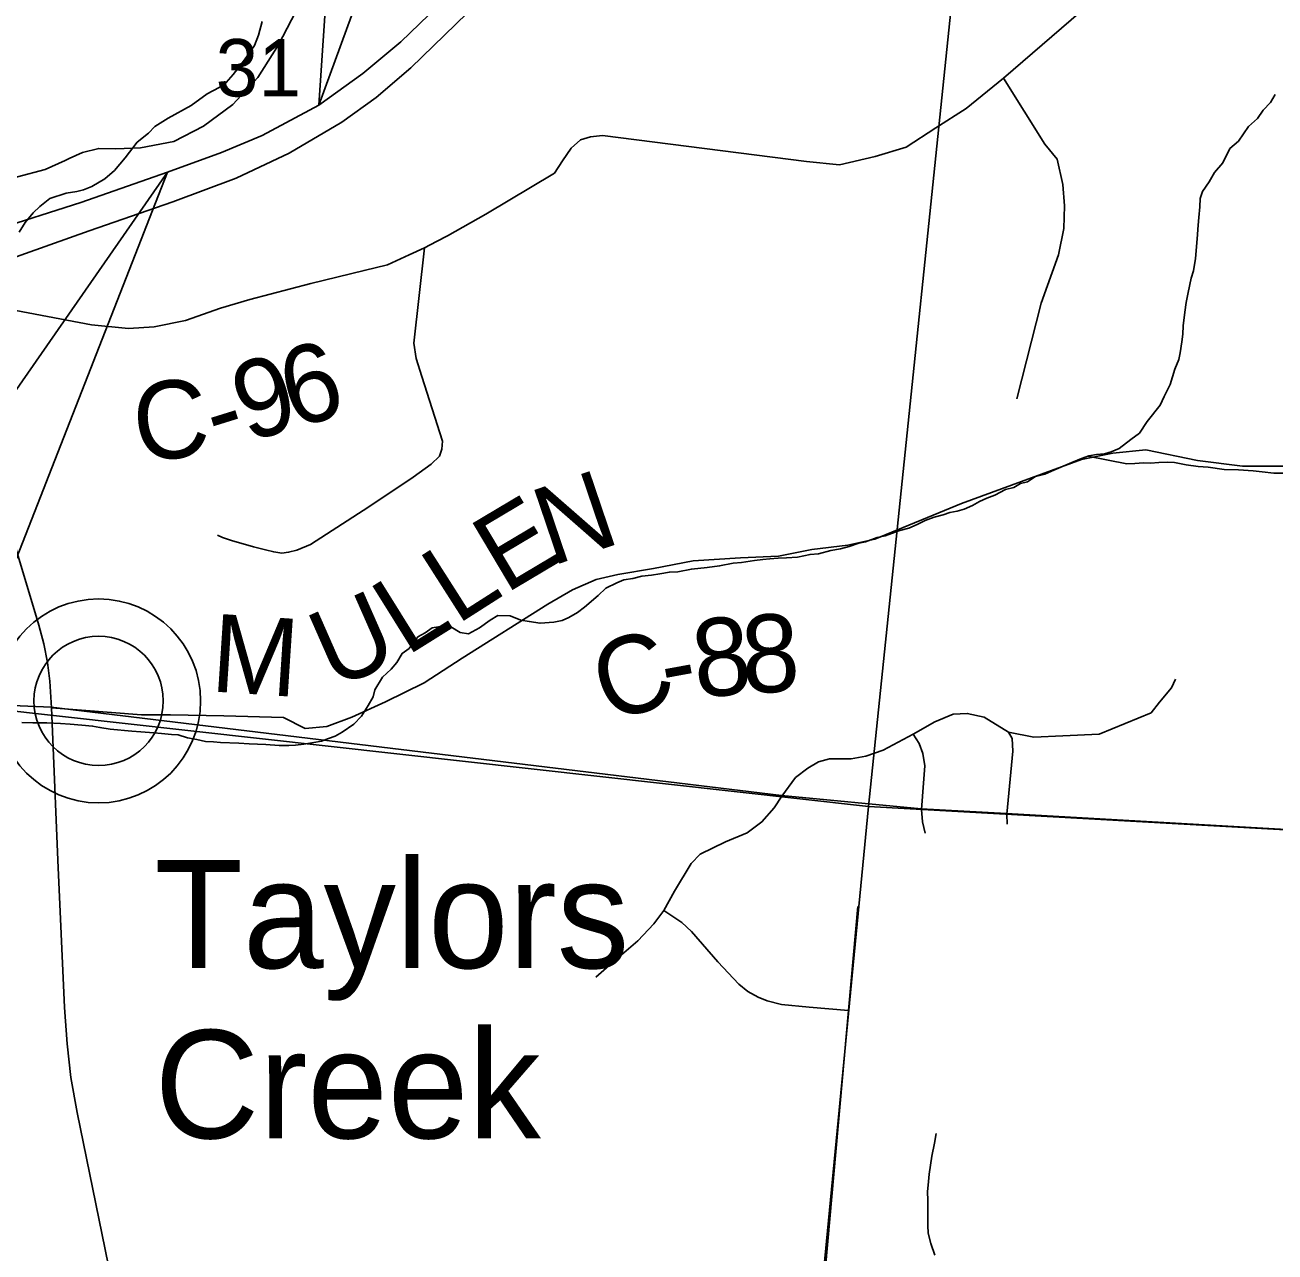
# Model space of a CAD drawing. Extents: x 0 to 34, y 0 to 22.
# Drawn here: x 5.748 to 6.66, y 16.77 to 17.665 of the extents above; entities that cross this region are included whole.
import ezdxf

# ---------------------------------------------------------------- set-up
doc = ezdxf.new("R2010")
doc.units = 0
for name, color, linetype in [('GM_X_County_Road', 7, 'Continuous'), ('GM_X_County_Road_Text', 7, 'Continuous'), ('GM_X_Interstate_Route', 7, 'Continuous'), ('GM_X_Minor_River', 7, 'Continuous'), ('GM_X_Section', 7, 'Continuous'), ('GM_X_Section_Text', 7, 'Continuous'), ('GM_X_State_Route', 7, 'Continuous'), ('GM_X_Township_Road', 7, 'Continuous'), ('GM_X_Unincorporated', 7, 'Continuous'), ('GM_X_Unincorporated_Location', 7, 'Continuous'), ('GM_X_Unincorporated_Text', 7, 'Continuous'), ('SH_Text', 7, 'Continuous')]:
    doc.layers.add(name, color=color, linetype=linetype)

msp = doc.modelspace()

# ---------------------------------------------------------------- linework, layer by layer
at = {"layer": 'GM_X_County_Road'}
for points in [[(6.04798, 17.50725), (6.0559, 17.51133), (6.08395, 17.52707), (6.13393, 17.55714), (6.1398, 17.56619), (6.1462, 17.5753), (6.15309, 17.58145), (6.16023, 17.58366), (6.16908, 17.58465), (6.31781, 17.56554), (6.342, 17.56324), (6.36798, 17.56924), (6.39057, 17.57612), (6.41227, 17.59023), (6.43434, 17.60433), (6.46163, 17.62634), (6.57278, 17.72256), (6.72198, 17.84461)], [(5.77999, 17.56768), (5.78978, 17.57206), (5.80163, 17.57517), (5.81415, 17.57484), (5.83201, 17.57551), (5.85643, 17.58018), (5.87799, 17.59139), (5.8993, 17.60716), (5.91767, 17.62681), (5.93275, 17.65073), (5.9704, 17.72344), (5.98341, 17.74095), (6.00335, 17.76245), (6.01656, 17.77389), (6.02847, 17.77889), (6.04374, 17.78229), (6.0549, 17.78769), (6.06951, 17.79452), (6.09226, 17.80945), (6.09391, 17.81053)], [(5.64082, 17.5926), (5.64833, 17.58055), (5.65231, 17.57312), (5.65628, 17.5638), (5.66412, 17.53856), (5.674, 17.50557), (5.68272, 17.47727), (5.68693, 17.46337), (5.68959, 17.45443), (5.75791, 17.22727), (5.76149, 17.21365), (5.76423, 17.20003), (5.76592, 17.18655), (5.76708, 17.16699)], [(5.66412, 17.53856), (5.74223, 17.55432), (5.7625, 17.55986), (5.77705, 17.56637), (5.77999, 17.56768)], [(5.68959, 17.45443), (5.70644, 17.45814), (5.72003, 17.45925), (5.74116, 17.45678), (5.79633, 17.44649), (5.82339, 17.44379), (5.84209, 17.44502), (5.86485, 17.44957), (5.89031, 17.45867), (5.91184, 17.46482), (5.95625, 17.47651), (5.99513, 17.48611), (6.01223, 17.49029), (6.02797, 17.49743), (6.03917, 17.50271), (6.04798, 17.50725)], [(5.76708, 17.16699), (5.83266, 17.16199), (5.85398, 17.16199), (5.8928, 17.16111), (5.9363, 17.15994), (5.9521, 17.15193), (5.96807, 17.15331), (5.98612, 17.16033), (6.01074, 17.17131), (6.03887, 17.18522), (6.06676, 17.20331), (6.12908, 17.2427), (6.14724, 17.25314), (6.16454, 17.26055), (6.18021, 17.26423), (6.20613, 17.26871), (6.23513, 17.27424), (6.2697, 17.27655), (6.29741, 17.27756), (6.32183, 17.28246), (6.3481, 17.2858), (6.36758, 17.29011), (6.43098, 17.31618), (6.51847, 17.3483), (6.54137, 17.35288), (6.56533, 17.35515), (6.60299, 17.34748), (6.63584, 17.34339), (6.65935, 17.3434), (6.68512, 17.34333)], [(5.76708, 17.16699), (5.768, 17.14401), (5.77185, 17.056), (5.77654, 16.94844), (5.77849, 16.92199), (5.78129, 16.8973), (5.78592, 16.8717), (5.81307, 16.73863)]]:
    msp.add_lwpolyline(points, dxfattribs=at)
at = {"layer": 'GM_X_Interstate_Route'}
for points in [[(5.701, 17.48307), (5.73372, 17.49345), (5.7946, 17.51503), (5.85567, 17.53626), (5.90185, 17.55339), (5.94058, 17.57163), (5.97894, 17.59435), (6.00389, 17.61223), (6.02922, 17.63383), (6.2508, 17.84908), (6.27799, 17.87552), (6.30182, 17.89712), (6.33087, 17.9217), (6.35917, 17.94367), (6.38263, 17.96192), (6.41503, 17.98427), (6.44967, 18.00661), (6.6787, 18.14664)], [(5.3928, 17.50788), (5.41776, 17.51208), (5.45304, 17.51122), (5.51103, 17.50896), (5.57644, 17.50431), (5.62112, 17.50202), (5.64961, 17.50293), (5.674, 17.50557), (5.67876, 17.50609), (5.70309, 17.50971), (5.72443, 17.51526), (5.78846, 17.53581), (5.85185, 17.55774), (5.89111, 17.57221), (5.92072, 17.5845), (5.96217, 17.60665), (5.99419, 17.6299), (6.02205, 17.65293), (6.25344, 17.87642)]]:
    msp.add_lwpolyline(points, dxfattribs=at)
at = {"layer": 'GM_X_Minor_River'}
for points in [[(5.74348, 17.51396), (5.7479, 17.52103), (5.75384, 17.52804), (5.75856, 17.53282), (5.76597, 17.53864), (5.77787, 17.54241), (5.78551, 17.54367), (5.79049, 17.54501), (5.79665, 17.54746), (5.80595, 17.55284), (5.81299, 17.55906), (5.82091, 17.56829), (5.82966, 17.57976), (5.83785, 17.58632), (5.84258, 17.5911), (5.85228, 17.59722), (5.86892, 17.60653), (5.8806, 17.61487), (5.88949, 17.6195), (5.89455, 17.62313), (5.89969, 17.62903), (5.90566, 17.6368), (5.91043, 17.6431), (5.91523, 17.65015), (5.91815, 17.65765), (5.92078, 17.66782)], [(6.4278, 17.31052), (6.43278, 17.31187), (6.43895, 17.3147), (6.44399, 17.31756), (6.44939, 17.32003), (6.45516, 17.32211), (6.46289, 17.32641), (6.46902, 17.32771), (6.47405, 17.33058), (6.47903, 17.33193), (6.48486, 17.33591), (6.49175, 17.33757), (6.49831, 17.34038), (6.50331, 17.34249), (6.51141, 17.34601), (6.51834, 17.34881), (6.52373, 17.3509), (6.52945, 17.35184), (6.53517, 17.3524), (6.54015, 17.35375), (6.54593, 17.35621), (6.55451, 17.36276), (6.56074, 17.36748), (6.56635, 17.37603), (6.57588, 17.38786), (6.57875, 17.39422), (6.58323, 17.4028), (6.58665, 17.41409), (6.58956, 17.42121), (6.59049, 17.42612), (6.59152, 17.43406), (6.59247, 17.43973), (6.59268, 17.4458), (6.59378, 17.45564), (6.59479, 17.46283), (6.59618, 17.47), (6.59844, 17.48056), (6.60014, 17.48583), (6.60159, 17.4949), (6.60285, 17.5093), (6.60357, 17.51915), (6.60415, 17.52483), (6.60479, 17.53241), (6.605, 17.53849), (6.6067, 17.54375), (6.6115, 17.5508), (6.61553, 17.5575), (6.62146, 17.56452), (6.62676, 17.57497), (6.63302, 17.58046), (6.64023, 17.59123), (6.64688, 17.59708), (6.65089, 17.60302), (6.65639, 17.60853), (6.65964, 17.6145)], [(6.52304, 17.35063), (6.55162, 17.34499), (6.55732, 17.34518), (6.56379, 17.34571), (6.56872, 17.34554), (6.57481, 17.34609), (6.58127, 17.34625), (6.5862, 17.34608), (6.59487, 17.34425), (6.60357, 17.34319), (6.61076, 17.34256), (6.62247, 17.34102), (6.63309, 17.34065), (6.6437, 17.3399), (6.65013, 17.3393), (6.65882, 17.33824), (6.66756, 17.33832)], [(5.74556, 17.15628), (5.75353, 17.15601), (5.76378, 17.15603), (5.77363, 17.15569), (5.78083, 17.15506), (5.78916, 17.15439), (5.79711, 17.15374), (5.80239, 17.1528), (5.80993, 17.1514), (5.82583, 17.15009), (5.83227, 17.14949), (5.84173, 17.14878), (5.84741, 17.1482), (5.8546, 17.14757), (5.85953, 17.1474), (5.86629, 17.14527), (5.87308, 17.14389), (5.87948, 17.14253), (5.88517, 17.14233), (5.89047, 17.14177), (5.90374, 17.14131), (5.91131, 17.14067), (5.92344, 17.14025), (5.93329, 17.13953), (5.94013, 17.13967), (5.94507, 17.13988), (5.95116, 17.14043), (5.95842, 17.1417), (5.96415, 17.14264), (5.96916, 17.14475), (5.97415, 17.14648), (5.97918, 17.14934), (5.98774, 17.15513), (5.99326, 17.16102), (5.99808, 17.16883), (6.00172, 17.17517), (6.00303, 17.18006), (6.00866, 17.18937), (6.01494, 17.19523), (6.0189, 17.20003), (6.02293, 17.20673), (6.02799, 17.21036), (6.03435, 17.21888), (6.03977, 17.22173), (6.04483, 17.22535), (6.05247, 17.22661), (6.05852, 17.22602), (6.06522, 17.22199), (6.07125, 17.22102), (6.07938, 17.2253), (6.08717, 17.23111), (6.0926, 17.23434), (6.1017, 17.23403), (6.10957, 17.23109), (6.11561, 17.23013), (6.12353, 17.22871), (6.13343, 17.22951), (6.13955, 17.23082), (6.14456, 17.23292), (6.15076, 17.23651), (6.15583, 17.24051), (6.16599, 17.2489), (6.1715, 17.25441), (6.1796, 17.25831), (6.18461, 17.26042), (6.1911, 17.26133), (6.19761, 17.26301), (6.20485, 17.2639), (6.21096, 17.26483), (6.21784, 17.26611), (6.22392, 17.26628), (6.23386, 17.26821), (6.24528, 17.26934), (6.25444, 17.27054), (6.26438, 17.27248), (6.27047, 17.27303), (6.28001, 17.2746), (6.28611, 17.27515), (6.29106, 17.27573), (6.29716, 17.27628), (6.30324, 17.27645), (6.31123, 17.27693), (6.32041, 17.2789), (6.3265, 17.27945), (6.33569, 17.28179), (6.34257, 17.28307), (6.34908, 17.28474), (6.356, 17.28717), (6.36097, 17.28814), (6.36943, 17.29126), (6.37517, 17.29258), (6.38593, 17.29639), (6.39244, 17.29806), (6.39861, 17.30089), (6.40441, 17.30373), (6.41094, 17.30616), (6.41745, 17.30784), (6.42245, 17.30957), (6.4278, 17.31052)], [(6.41135, 16.76767), (6.40861, 16.77613), (6.40659, 16.7838), (6.40641, 16.7895), (6.40628, 16.79673), (6.40628, 16.80775), (6.40611, 16.81383), (6.40675, 16.82141), (6.40731, 16.82671), (6.40929, 16.83994), (6.41113, 16.84938), (6.41252, 16.85655)]]:
    msp.add_lwpolyline(points, dxfattribs=at)
at = {"layer": 'GM_X_Section'}
for points in [[(5.47315, 18.19984), (6.46507, 18.07992), (6.36313, 17.09514), (5.37854, 17.20503)], [(6.46507, 18.07992), (7.31107, 18.01998), (7.27109, 17.04431), (6.36313, 17.09514)], [(5.37854, 17.20503), (6.36313, 17.09514), (6.26802, 16.11095), (5.28125, 16.20876)], [(7.27109, 17.04431), (7.20645, 16.05068), (6.26802, 16.11095), (6.36313, 17.09514)]]:
    msp.add_lwpolyline(points, close=True, dxfattribs=at)
at = {"layer": 'GM_X_State_Route'}
for points in [[(4.80053, 17.26765), (5.26325, 17.21727), (5.37857, 17.20471), (5.65441, 17.17428), (5.66212, 17.17343), (5.68707, 17.17089), (5.76684, 17.16751), (6.29973, 17.1032), (6.40151, 17.09347), (6.46374, 17.08993), (6.75273, 17.07349)], [(8.9, 14.1), (8.9, 16.86165), (8.87084, 16.86594), (8.72454, 16.88714), (7.84984, 16.99282), (7.58925, 17.01579), (7.54703, 17.01951), (7.29572, 17.04162), (7.269, 17.04472), (7.04958, 17.05695), (6.75273, 17.07349), (6.46374, 17.08993), (6.40151, 17.09347), (6.29973, 17.1032), (5.76684, 17.16751), (5.68707, 17.17089), (5.66212, 17.17343), (5.65441, 17.17428), (5.37857, 17.20471), (5.30005, 16.42444), (5.24989, 15.92598), (5.17149, 15.14686)]]:
    msp.add_lwpolyline(points, dxfattribs=at)
at = {"layer": 'GM_X_Township_Road'}
msp.add_line((6.46414, 17.08219), (6.46398, 17.08941), dxfattribs=at)
for points in [[(6.46163, 17.62634), (6.49182, 17.57817), (6.50061, 17.56726), (6.50491, 17.54882), (6.50602, 17.53337), (6.50546, 17.51683), (6.50161, 17.49752), (6.48892, 17.46222), (6.47138, 17.39235)], [(5.8882, 17.29292), (5.89184, 17.29134), (5.8984, 17.28908), (5.91437, 17.28452), (5.92322, 17.28223), (5.9292, 17.28081), (5.93519, 17.27995), (5.94004, 17.28053), (5.94603, 17.28195), (5.95601, 17.28623), (5.9985, 17.31361), (6.03102, 17.33528), (6.04413, 17.34469), (6.05012, 17.35068), (6.05183, 17.35582), (6.0524, 17.36152), (6.03729, 17.40886), (6.03301, 17.42198), (6.0313, 17.4331), (6.03917, 17.50271)], [(6.29997, 17.10268), (6.3098, 17.11616), (6.31875, 17.12305), (6.32667, 17.12753), (6.33459, 17.12994), (6.35043, 17.12994), (6.3611, 17.13166), (6.37385, 17.13614), (6.39554, 17.14784), (6.41138, 17.1568), (6.42481, 17.16231), (6.43514, 17.163), (6.44754, 17.16024), (6.46522, 17.1493), (6.48374, 17.14559), (6.50473, 17.14662), (6.53128, 17.14786), (6.56915, 17.1635), (6.57533, 17.17111), (6.58418, 17.18161), (6.58706, 17.18799)], [(6.40175, 17.09295), (6.40312, 17.11203), (6.40415, 17.12477), (6.40277, 17.13372), (6.40002, 17.14096), (6.39554, 17.14784)], [(6.46398, 17.08941), (6.4683, 17.13551), (6.46789, 17.14477), (6.46522, 17.1493)], [(6.16413, 16.9705), (6.17791, 16.98255), (6.19478, 16.99702), (6.20649, 17.00941), (6.2139, 17.0193), (6.22164, 17.03317), (6.23369, 17.05349), (6.24024, 17.06038), (6.25883, 17.06933), (6.27467, 17.07587), (6.28535, 17.08379), (6.2943, 17.09412), (6.29997, 17.10268)], [(6.40449, 17.07553), (6.40243, 17.08379), (6.40175, 17.09295)], [(6.2139, 17.0193), (6.22691, 17.0105), (6.23394, 17.00382), (6.25329, 16.98166), (6.26841, 16.96548), (6.2751, 16.96021), (6.28248, 16.95599), (6.28917, 16.95317), (6.29972, 16.95071), (6.31977, 16.9486), (6.34852, 16.94618)], [(6.33035, 16.74261), (6.34852, 16.94618), (6.35529, 17.02211)]]:
    msp.add_lwpolyline(points, dxfattribs=at)
at = {"layer": 'GM_X_Unincorporated'}
for radius in [0.0744, 0.04716]:
    msp.add_circle((5.80149, 17.17208), radius, dxfattribs=at)
at = {"layer": 'GM_X_Unincorporated_Location'}
msp.add_line((5.80149, 17.17208), (5.80149, 17.17208), dxfattribs=at)
at = {"layer": 'SH_Text'}
for points in [[(6.0065, 18.26935), (5.96217, 17.60665), (6.20431, 18.26935)], [(5.63769, 17.01138), (5.85185, 17.55774), (5.63769, 17.2501)]]:
    msp.add_lwpolyline(points, close=True, dxfattribs=at)
msp.add_lwpolyline([(5.85185, 17.55774), (5.89111, 17.57221), (5.92072, 17.5845), (5.96217, 17.60665)], dxfattribs=at)

# ---------------------------------------------------------------- texts
at = {"layer": 'GM_X_County_Road_Text'}
for s, rotation, p in [('6', 15.32563, (5.94303, 17.37068)), ('9', 17.08168, (5.91001, 17.36052)), ('C', 6.30819, (5.82978, 17.34605)), ('-', 17.28295, (5.88778, 17.35361)), ('N', 18.74309, (6.1317, 17.2702)), ('E', 30.76182, (6.09803, 17.24977)), ('L', 32.55248, (6.06261, 17.22715)), ('U', 23.76243, (5.97255, 17.18009)), ('L', 31.97721, (6.02604, 17.20432)), ('M', 356.26103, (5.88246, 17.17907)), ('8', 5.80717, (6.23765, 17.17398)), ('8', 2.68101, (6.27165, 17.17746)), ('C', 18.9777, (6.17393, 17.15534)), ('-', 10.38409, (6.21588, 17.16994))]:
    msp.add_text(s, height=0.05682, rotation=rotation, dxfattribs=at).set_placement(p)
at = {"layer": 'GM_X_Section_Text'}
msp.add_text('31', height=0.041856, rotation=0.00001, dxfattribs=at).set_placement((5.88688, 17.61307))
at = {"layer": 'GM_X_Unincorporated_Text'}
for s, p in [('Taylors', (5.8423, 16.97714)), ('Creek', (5.8423, 16.85297))]:
    msp.add_text(s, height=0.078977, rotation=0.00001, dxfattribs=at).set_placement(p)

doc.saveas('drawing.dxf')
